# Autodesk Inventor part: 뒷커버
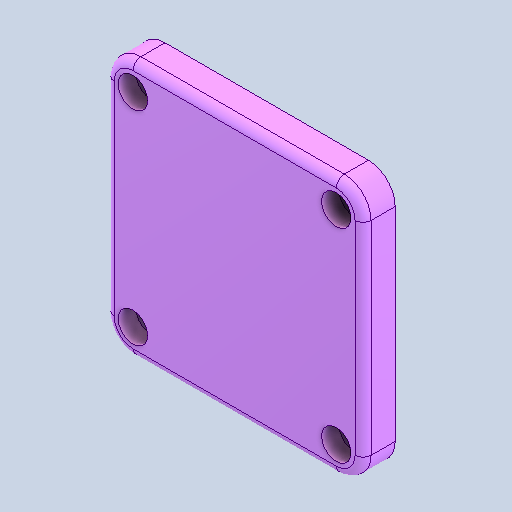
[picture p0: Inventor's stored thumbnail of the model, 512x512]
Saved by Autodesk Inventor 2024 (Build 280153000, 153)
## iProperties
Created: 2025-05
Part Number: 뒷커버
Material: 알루미늄 6061
Document SubType Name: Modeling
Designer: 11
Density: 2.7 g/cm^3
Appearance: 기본값
Author: jhkim
Sending System: Autodesk Inventor 2026
Preprocessor: ST-DEVELOPER v20.1
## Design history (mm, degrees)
node "뒷커버1"
node "솔리드2"
node "솔리드1"
